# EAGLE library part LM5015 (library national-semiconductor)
High Voltage Monolithic Two-Switch Forward DC-DC Regulator Source: http://cache.national.com/ds/LM/LM5015.pdf
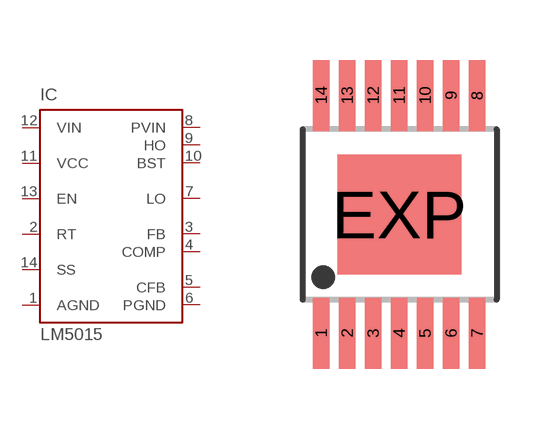
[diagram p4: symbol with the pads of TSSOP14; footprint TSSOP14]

Designator prefix IC

## LM5015 (MPN: LM5015MH/NOPB; OC_FARNELL: 1535370; OC_NEWARK: 64M7033)  [TSSOP14]
1  AGND  pwr
2  RT  in
3  FB  in
4  COMP  in
5  CFB  pwr
6  PGND  pwr
7  LO  out
8  PVIN  in
9  HO  out
10  BST  pas
11  VCC  pwr
12  VIN  in
13  EN  in
14  SS  in

## Footprint TSSOP14 (pad centres in mm)
14-Lead Exposed Pad Package NS Package Number MXA14A Source: http://cache.national.com/ds/LM/LM5015.pdf
smd 0.42 x 1.78: 1 -1.95,-2.975; 2 -1.3,-2.975; 3 -0.65,-2.975; 4 0,-2.975; 5 0.65,-2.975; 6 1.3,-2.975; 7 1.95,-2.975; 8 1.95,2.975; 9 1.3,2.975; 10 0.65,2.975; 11 0,2.975; 12 -0.65,2.975; 13 -1.3,2.975; 14 -1.95,2.975
smd 3.1 x 3: EXP 0,0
